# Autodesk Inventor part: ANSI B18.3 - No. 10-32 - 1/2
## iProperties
Comments: To add or edit properties for Autodesk Inventor files, use iProperties.
Created: 2005-02
Part Number: ANSI B18.3 - No. 10-32 - 1/2
Vendor: Autodesk Inc.
Document SubType Name: Modeling
Designer: John Blackburn
Material: Default
Description: Hexagon Socket Button Head Cap Screw
Standard: ANSI B18.3
Size Designation: No. 10-32 - 1/2
Alert: To add or edit properties for Autodesk Inventor files, use iProperties.
Control State: 0
Master: False
Checked Out: False
Shininess: 64.0
Length Units: 11272
Angle Units: 11279
Time Units: 11290
Mass Units: 11286
Length Display Precision: 3
Angle Display Precision: 2
Compacted: True
EGR: 4
Classification: un/spsc 31161501
Density: 0.0
Volumn: 0.0
Area: 0.0
PropertySet Name: Model Information
Author: John Blackburn
Revision Number: 8
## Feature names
1. Body [Revolution]
2. Slot [Extrusion]
3. Fillet1
4. Chamfer1
